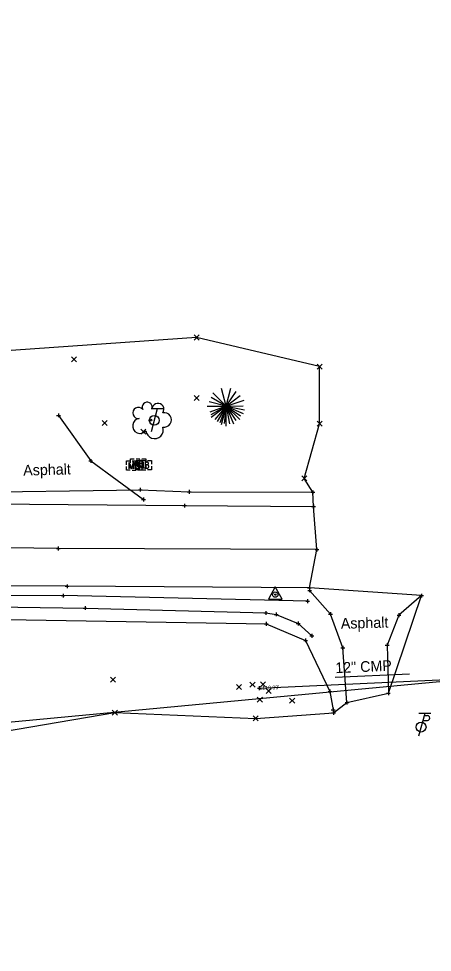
# Model space of a CAD drawing. Extents: x 146022 to 147632, y 437624 to 440659.
# Drawn here: x 147365.2 to 147473.8, y 438520.2 to 438765.5 of the extents above; entities that cross this region are included whole.
import ezdxf

# ---------------------------------------------------------------- set-up
doc = ezdxf.new("R2010")
doc.units = 0
for name, color, linetype in [('_CIVIL_CONSTRUCTION', 7, 'Continuous'), ('DR_P_Paved_Gutter', 7, 'Continuous'), ('DR_X_Storm_Sewer', 7, 'Continuous'), ('DR_X_Text', 7, 'Continuous'), ('DT_X_Contour_Major', 7, 'Continuous'), ('DT_X_Spot_Elev', 7, 'Continuous'), ('DT_X_Void', 7, 'Continuous'), ('PF_X_Ground_Line', 7, 'Continuous'), ('PV_P_Curb', 7, 'Continuous'), ('PV_P_Joint', 7, 'Continuous'), ('RD_P_Anchor_Assembly', 7, 'Continuous'), ('RD_P_GR_Lt_Replaced', 7, 'Continuous'), ('SC_Scratch1', 7, 'Continuous'), ('SC_Scratch3', 7, 'Continuous'), ('SV_X_Terrain_Boundary', 7, 'Continuous'), ('UT_X_Overhead_Cable_TV', 7, 'Continuous'), ('UT_X_Overhead_Electric', 7, 'Continuous')]:
    doc.layers.add(name, color=color, linetype=linetype)

msp = doc.modelspace()

# ---------------------------------------------------------------- linework, layer by layer
at = {"layer": '_CIVIL_CONSTRUCTION'}
for p, q in [((147411.27, 438681.05), (147412.61, 438682.38)), ((147411.27, 438682.38), (147412.61, 438681.05)), ((147379.11, 438675.34), (147380.44, 438676.67)), ((147379.11, 438676.67), (147380.44, 438675.34)), ((147443.56, 438673.4), (147444.89, 438674.73)), ((147443.56, 438674.73), (147444.89, 438673.4)), ((147411.28, 438665.13), (147412.61, 438666.46)), ((147411.28, 438666.46), (147412.61, 438665.13)), ((147387.13, 438658.62), (147388.46, 438659.95)), ((147387.13, 438659.95), (147388.46, 438658.62)), ((147443.58, 438658.4), (147444.91, 438659.73)), ((147443.58, 438659.73), (147444.91, 438658.4)), ((147397.27, 438656.35), (147398.6, 438657.68)), ((147397.27, 438657.68), (147398.6, 438656.35)), ((147439.54, 438644.06), (147440.88, 438645.39)), ((147439.54, 438645.39), (147440.88, 438644.06)), ((147389.33, 438591.14), (147390.66, 438592.48)), ((147389.33, 438592.48), (147390.66, 438591.14)), ((147422.38, 438589.28), (147423.71, 438590.61)), ((147422.38, 438590.61), (147423.71, 438589.28)), ((147425.94, 438589.88), (147427.27, 438591.22)), ((147425.94, 438591.22), (147427.27, 438589.88)), ((147428.71, 438589.94), (147430.04, 438591.28)), ((147428.71, 438591.28), (147430.04, 438589.94)), ((147430.16, 438588.2), (147431.5, 438589.53)), ((147430.16, 438589.53), (147431.5, 438588.2)), ((147427.87, 438585.93), (147429.2, 438587.27)), ((147427.87, 438587.27), (147429.2, 438585.93)), ((147436.36, 438585.66), (147437.7, 438587)), ((147436.36, 438587), (147437.7, 438585.66)), ((147389.8, 438582.52), (147391.14, 438583.85)), ((147389.8, 438583.85), (147391.14, 438582.52)), ((147426.81, 438581.01), (147428.14, 438582.34)), ((147426.81, 438582.34), (147428.14, 438581.01))]:
    msp.add_line(p, q, dxfattribs=at)
at = {"layer": 'DR_P_Paved_Gutter'}
msp.add_lwpolyline([(147090.74, 438611.98), (147096.12, 438612.12), (147118.78, 438612.16), (147162.43, 438612.19), (147208.09, 438612.03), (147262.63, 438611.82), (147323.61, 438611.5), (147382.66, 438610.66), (147430.09, 438609.36), (147432.84, 438608.99), (147438.6, 438606.61), (147442.2, 438603.35)], dxfattribs=at)
at = {"layer": 'DR_X_Storm_Sewer'}
for p in [(147070.7, 438553.26), (147428.39, 438589.62)]:
    msp.add_line(p, (147483.94, 438592.14), dxfattribs=at)
at = {"layer": 'DR_X_Text'}
msp.add_line((147467.8, 438593.31), (147448.35, 438592.43), dxfattribs=at)
at = {"layer": 'DT_X_Contour_Major'}
for p, q in [((147471.84, 438582.99), (147470.23, 438576.99)), ((147473.44, 438582.99), (147470.24, 438582.99)), ((147471.34, 438581.11), (147472.53, 438581.11)), ((147471.68, 438582.39), (147472.53, 438582.39))]:
    msp.add_line(p, q, dxfattribs=at)
msp.add_circle((147470.87, 438579.39), 1.3, dxfattribs=at)
msp.add_arc((147472.54, 438581.75), 0.638, 268.8767, 91.1233, dxfattribs=at)
at = {"layer": 'DT_X_Spot_Elev'}
for p, q in [((147395.01, 438649.28), (147396.01, 438649.28)), ((147396.07, 438649.81), (147397.07, 438649.81)), ((147397.56, 438649.42), (147398.57, 438649.42)), ((147395.01, 438646.84), (147396.01, 438646.84)), ((147395.52, 438648.06), (147395.52, 438648.06)), ((147396.07, 438647.36), (147397.07, 438647.36)), ((147396.58, 438648.58), (147396.58, 438648.58)), ((147397.56, 438646.97), (147398.57, 438646.97)), ((147398.08, 438648.2), (147398.08, 438648.2))]:
    msp.add_line(p, q, dxfattribs=at)
for points in [[(147393.52, 438648.31), (147393.52, 438649.28), (147394.49, 438649.28)], [(147394.23, 438647.26), (147394.23, 438648.86), (147394.81, 438647.26), (147395.36, 438648.86), (147395.36, 438647.26)], [(147394.58, 438648.84), (147394.58, 438649.81), (147395.55, 438649.81)], [(147395.28, 438647.78), (147395.28, 438649.38), (147395.86, 438647.78), (147396.42, 438649.38), (147396.42, 438647.78)], [(147396.54, 438648.13), (147396.61, 438648.19), (147396.65, 438648.23), (147396.67, 438648.27), (147396.68, 438648.29), (147396.71, 438648.34), (147396.72, 438648.38), (147396.75, 438648.47), (147396.75, 438648.51), (147396.75, 438648.56), (147396.73, 438648.63), (147396.71, 438648.7), (147396.67, 438648.75), (147396.61, 438648.8), (147396.56, 438648.82), (147396.53, 438648.84), (147396.47, 438648.86), (147395.85, 438648.86), (147395.85, 438647.26), (147396.54, 438647.26), (147396.63, 438647.31), (147396.71, 438647.37), (147396.77, 438647.48), (147396.81, 438647.59), (147396.82, 438647.7), (147396.82, 438647.78), (147396.8, 438647.85), (147396.75, 438647.97), (147396.68, 438648.04), (147396.54, 438648.13), (147395.85, 438648.13)], [(147396.08, 438648.45), (147396.08, 438649.42), (147397.05, 438649.42)], [(147396.53, 438649.28), (147397.52, 438649.28), (147397.52, 438648.31)], [(147396.78, 438647.4), (147396.78, 438649), (147397.36, 438647.4), (147397.91, 438649), (147397.91, 438647.4)], [(147397.6, 438648.65), (147397.67, 438648.72), (147397.7, 438648.75), (147397.73, 438648.79), (147397.74, 438648.82), (147397.77, 438648.87), (147397.78, 438648.91), (147397.8, 438648.99), (147397.8, 438649.03), (147397.8, 438649.08), (147397.79, 438649.16), (147397.77, 438649.22), (147397.73, 438649.27), (147397.67, 438649.32), (147397.61, 438649.35), (147397.59, 438649.36), (147397.53, 438649.38), (147396.91, 438649.38), (147396.91, 438647.78), (147397.6, 438647.78), (147397.69, 438647.83), (147397.77, 438647.9), (147397.83, 438648), (147397.87, 438648.11), (147397.88, 438648.23), (147397.88, 438648.3), (147397.85, 438648.38), (147397.8, 438648.49), (147397.74, 438648.57), (147397.6, 438648.65), (147396.91, 438648.65)], [(147397.59, 438649.81), (147398.58, 438649.81), (147398.58, 438648.84)], [(147399.1, 438648.26), (147399.16, 438648.33), (147399.2, 438648.37), (147399.22, 438648.4), (147399.24, 438648.43), (147399.26, 438648.48), (147399.27, 438648.52), (147399.3, 438648.6), (147399.3, 438648.64), (147399.3, 438648.69), (147399.29, 438648.77), (147399.26, 438648.83), (147399.22, 438648.88), (147399.16, 438648.93), (147399.11, 438648.96), (147399.08, 438648.97), (147399.02, 438649), (147398.4, 438649), (147398.4, 438647.4), (147399.1, 438647.4), (147399.18, 438647.45), (147399.26, 438647.51), (147399.32, 438647.61), (147399.36, 438647.72), (147399.37, 438647.84), (147399.37, 438647.91), (147399.35, 438647.99), (147399.3, 438648.1), (147399.24, 438648.18), (147399.1, 438648.26), (147398.4, 438648.26)], [(147399.08, 438649.42), (147400.08, 438649.42), (147400.08, 438648.45)], [(147394.49, 438646.84), (147393.52, 438646.84), (147393.52, 438647.81)], [(147395.55, 438647.36), (147394.58, 438647.36), (147394.58, 438648.33)], [(147397.05, 438646.97), (147396.08, 438646.97), (147396.08, 438647.94)], [(147397.52, 438647.81), (147397.52, 438646.84), (147396.53, 438646.84)], [(147398.58, 438648.33), (147398.58, 438647.36), (147397.59, 438647.36)], [(147400.08, 438647.94), (147400.08, 438646.97), (147399.08, 438646.97)]]:
    msp.add_lwpolyline(points, dxfattribs=at)
at = {"layer": 'DT_X_Void'}
for p, q in [((147419.68, 438663.68), (147418.45, 438668.29)), ((147419.68, 438663.68), (147420.94, 438668.38)), ((147419.68, 438663.68), (147415.77, 438665.98)), ((147419.68, 438663.68), (147416.19, 438667.17)), ((147419.68, 438663.68), (147422.34, 438667.57)), ((147419.68, 438663.68), (147423.34, 438666.49)), ((147414.75, 438663.68), (147419.68, 438663.68)), ((147419.68, 438663.68), (147415.27, 438664.86)), ((147419.68, 438663.68), (147415.39, 438662.12)), ((147419.68, 438663.68), (147415.7, 438661.4)), ((147419.68, 438663.68), (147415.77, 438660.69)), ((147419.68, 438663.68), (147416.74, 438660.21)), ((147419.68, 438663.68), (147417.36, 438659.67)), ((147419.68, 438663.68), (147418.02, 438659.34)), ((147419.68, 438663.68), (147418.42, 438658.82)), ((147419.68, 438663.68), (147419.14, 438659.09)), ((147419.68, 438663.68), (147424.42, 438665.29)), ((147419.68, 438663.68), (147424.19, 438663.77)), ((147419.68, 438658.44), (147419.68, 438663.68)), ((147419.68, 438663.68), (147420.6, 438659.04)), ((147419.68, 438663.68), (147421.61, 438659.01)), ((147419.68, 438663.68), (147422.22, 438659.89)), ((147419.68, 438663.68), (147423.27, 438660.16)), ((147419.68, 438663.68), (147423.5, 438661.13)), ((147419.68, 438663.68), (147424.15, 438661.74)), ((147419.68, 438663.68), (147424.51, 438662.72))]:
    msp.add_line(p, q, dxfattribs=at)
msp.add_circle((147399.96, 438660.03), 0.24, dxfattribs=at)
for centre, radius, start, end in [((147396.65, 438661.9), 1.47, 39.0625, 279.5412), ((147398.98, 438663.4), 1.32, 354.0047, 205.9741), ((147401.79, 438662.86), 1.55, 323.83, 165.0376), ((147403.42, 438660.07), 1.91, 259.1453, 101.4596), ((147397.11, 438658.48), 1.97, 96.1722, 320.5737), ((147400.91, 438657.43), 2.28, 184.9476, 19.4572)]:
    msp.add_arc(centre, radius, start, end, dxfattribs=at)
at = {"layer": 'PF_X_Ground_Line'}
msp.add_lwpolyline([(147090.56, 438608.28), (147100.12, 438605.93), (147134.16, 438606.88), (147169.46, 438609.09), (147200.89, 438609.42), (147231.43, 438607.76), (147285.62, 438608.05), (147340.88, 438607.99), (147430.19, 438606.52), (147440.56, 438602.17), (147446.94, 438588.76), (147447.8, 438583.92), (147447.86, 438583.13)], dxfattribs=at)
at = {"layer": 'PV_P_Curb'}
msp.add_lwpolyline([(147443.52, 438625.99), (147375.64, 438626.29), (147305.7, 438627.27), (147243.72, 438626.94), (147218.64, 438627.35)], dxfattribs=at)
at = {"layer": 'PV_P_Joint'}
msp.add_lwpolyline([(147430.78, 438613.01), (147434.38, 438613.01), (147432.58, 438616.23)], close=True, dxfattribs=at)
for radius in [0.7, 0.16]:
    msp.add_circle((147432.58, 438614.17), radius, dxfattribs=at)
at = {"layer": 'RD_P_Anchor_Assembly'}
for p, q in [((147375.18, 438661.25), (147376.18, 438661.25)), ((147375.68, 438661.75), (147375.68, 438660.75)), ((147375.68, 438661.25), (147375.68, 438661.25)), ((147383.64, 438649.3), (147384.64, 438649.3)), ((147384.14, 438649.8), (147384.14, 438648.8)), ((147384.14, 438649.3), (147384.14, 438649.3)), ((147396.66, 438641.73), (147397.66, 438641.73)), ((147397.16, 438642.23), (147397.16, 438641.23)), ((147397.16, 438641.73), (147397.16, 438641.73)), ((147409.97, 438641.67), (147409.97, 438640.67)), ((147442.47, 438641.55), (147442.47, 438640.55)), ((147397.5, 438639.17), (147398.5, 438639.17)), ((147398, 438639.67), (147398, 438638.67)), ((147398, 438639.17), (147398, 438639.17)), ((147409.47, 438641.17), (147410.47, 438641.17)), ((147409.97, 438641.17), (147409.97, 438641.17)), ((147441.97, 438641.05), (147442.97, 438641.05)), ((147442.47, 438641.05), (147442.47, 438641.05)), ((147408.26, 438637.55), (147409.26, 438637.55)), ((147408.76, 438638.05), (147408.76, 438637.05)), ((147408.76, 438637.55), (147408.76, 438637.55)), ((147442.13, 438637.34), (147443.13, 438637.34)), ((147442.63, 438637.84), (147442.63, 438636.84)), ((147442.63, 438637.34), (147442.63, 438637.34)), ((147375.64, 438626.79), (147375.64, 438625.79)), ((147375.14, 438626.29), (147376.14, 438626.29)), ((147375.64, 438626.29), (147375.64, 438626.29)), ((147443.02, 438625.99), (147444.02, 438625.99)), ((147443.52, 438626.49), (147443.52, 438625.49)), ((147443.52, 438625.99), (147443.52, 438625.99)), ((147377.93, 438616.86), (147377.93, 438615.86)), ((147376.87, 438614.41), (147376.87, 438613.41)), ((147377.43, 438616.36), (147378.43, 438616.36)), ((147377.93, 438616.36), (147377.93, 438616.36)), ((147441.04, 438616), (147442.04, 438616)), ((147441.1, 438615.29), (147442.1, 438615.29)), ((147441.54, 438616.5), (147441.54, 438615.5)), ((147441.54, 438616), (147441.54, 438616)), ((147441.6, 438615.79), (147441.6, 438614.79)), ((147441.6, 438615.29), (147441.6, 438615.29)), ((147470.97, 438614.42), (147470.97, 438613.42)), ((147376.37, 438613.91), (147377.37, 438613.91)), ((147376.87, 438613.91), (147376.87, 438613.91)), ((147440.58, 438612.46), (147441.58, 438612.46)), ((147441.08, 438612.96), (147441.08, 438611.96)), ((147441.08, 438612.46), (147441.08, 438612.46)), ((147470.47, 438613.92), (147471.47, 438613.92)), ((147470.97, 438613.92), (147470.97, 438613.92)), ((147382.16, 438610.66), (147383.16, 438610.66)), ((147382.66, 438611.16), (147382.66, 438610.16)), ((147382.66, 438610.66), (147382.66, 438610.66)), ((147430.09, 438609.86), (147430.09, 438608.86)), ((147432.84, 438609.49), (147432.84, 438608.49)), ((147447.07, 438609.58), (147447.07, 438608.58)), ((147429.59, 438609.36), (147430.59, 438609.36)), ((147430.09, 438609.36), (147430.09, 438609.36)), ((147430.19, 438607.02), (147430.19, 438606.02)), ((147432.34, 438608.99), (147433.34, 438608.99)), ((147432.84, 438608.99), (147432.84, 438608.99)), ((147438.6, 438607.11), (147438.6, 438606.11)), ((147446.57, 438609.08), (147447.57, 438609.08)), ((147447.07, 438609.08), (147447.07, 438609.08)), ((147464.55, 438608.79), (147465.55, 438608.79)), ((147465.05, 438609.29), (147465.05, 438608.29)), ((147465.05, 438608.79), (147465.05, 438608.79)), ((147429.69, 438606.52), (147430.69, 438606.52)), ((147430.19, 438606.52), (147430.19, 438606.52)), ((147438.1, 438606.61), (147439.1, 438606.61)), ((147438.6, 438606.61), (147438.6, 438606.61)), ((147440.06, 438602.17), (147441.06, 438602.17)), ((147440.56, 438602.67), (147440.56, 438601.67)), ((147440.56, 438602.17), (147440.56, 438602.17)), ((147441.7, 438603.35), (147442.7, 438603.35)), ((147442.2, 438603.85), (147442.2, 438602.85)), ((147442.2, 438603.35), (147442.2, 438603.35)), ((147449.84, 438600.23), (147450.84, 438600.23)), ((147450.34, 438600.73), (147450.34, 438599.73)), ((147450.34, 438600.23), (147450.34, 438600.23)), ((147461.45, 438600.89), (147462.45, 438600.89)), ((147461.95, 438601.39), (147461.95, 438600.39)), ((147461.95, 438600.89), (147461.95, 438600.89)), ((147446.44, 438588.76), (147447.44, 438588.76)), ((147446.94, 438589.26), (147446.94, 438588.26)), ((147446.94, 438588.76), (147446.94, 438588.76)), ((147461.79, 438588.25), (147462.79, 438588.25)), ((147462.29, 438588.75), (147462.29, 438587.75)), ((147462.29, 438588.25), (147462.29, 438588.25)), ((147450.91, 438585.81), (147451.91, 438585.81)), ((147451.41, 438586.31), (147451.41, 438585.31)), ((147451.41, 438585.81), (147451.41, 438585.81)), ((147447.3, 438583.92), (147448.3, 438583.92)), ((147447.36, 438583.13), (147448.36, 438583.13)), ((147447.8, 438584.42), (147447.8, 438583.42)), ((147447.8, 438583.92), (147447.8, 438583.92)), ((147447.86, 438583.63), (147447.86, 438582.63)), ((147447.86, 438583.13), (147447.86, 438583.13))]:
    msp.add_line(p, q, dxfattribs=at)
at = {"layer": 'RD_P_GR_Lt_Replaced'}
for points in [[(147168.32, 438765.47), (147172.75, 438740.93), (147180.87, 438702.22), (147190.04, 438671.47), (147197.36, 438659.31), (147205.75, 438651.31), (147223.43, 438643.49), (147231.5, 438641.71), (147288.88, 438640.47), (147347.57, 438641.04), (147397.16, 438641.73), (147409.97, 438641.17), (147442.47, 438641.05)], [(147441.08, 438612.46), (147376.87, 438613.91), (147318.39, 438613.89), (147243.87, 438614.42), (147218.85, 438614.27), (147160.23, 438614.06), (147116.28, 438615.1), (147116.37, 438616.32), (147097.65, 438616.22), (147092.09, 438613.53), (147091.95, 438613.68)]]:
    msp.add_lwpolyline(points, dxfattribs=at)
at = {"layer": 'SC_Scratch1'}
for points in [[(147375.68, 438661.25), (147384.14, 438649.3), (147398, 438639.17)], [(147451.41, 438585.81), (147450.34, 438600.23), (147447.07, 438609.08), (147441.6, 438615.29)], [(147470.97, 438613.92), (147465.05, 438608.79), (147461.95, 438600.89), (147462.29, 438588.25)]]:
    msp.add_lwpolyline(points, dxfattribs=at)
at = {"layer": 'SC_Scratch3'}
for points in [[(147231.86, 438637.99), (147288.59, 438637.9), (147347.36, 438637.73), (147357.85, 438637.99), (147408.76, 438637.55), (147442.63, 438637.34)], [(147441.54, 438616), (147377.93, 438616.36), (147319.33, 438616.54), (147244.05, 438616.81), (147219.36, 438616.86), (147159.11, 438616.91), (147088.59, 438616.85)]]:
    msp.add_lwpolyline(points, dxfattribs=at)
at = {"layer": 'SV_X_Terrain_Boundary'}
msp.add_lwpolyline([(147113.81, 438520.22), (147177.01, 438554.45), (147231.16, 438565.21), (147265.76, 438561.91), (147390.47, 438583.18), (147427.48, 438581.67), (147447.86, 438583.13), (147451.41, 438585.81), (147462.29, 438588.25), (147470.97, 438613.92), (147441.54, 438616), (147443.52, 438625.99), (147442.63, 438637.34), (147442.47, 438641.05), (147440.21, 438644.72), (147444.24, 438659.07), (147444.23, 438674.06), (147411.94, 438681.71), (147340.71, 438676.77), (147269.57, 438686.84), (147201.59, 438744.19), (147187.75, 438754.72), (147168.32, 438765.47), (147156.85, 438763.96)], dxfattribs=at)
at = {"layer": 'UT_X_Overhead_Cable_TV'}
for p, q in [((147401.62, 438662.95), (147400.01, 438656.95)), ((147403.22, 438662.95), (147400.02, 438662.95))]:
    msp.add_line(p, q, dxfattribs=at)
msp.add_circle((147400.82, 438659.95), 1.3, dxfattribs=at)
at = {"layer": 'UT_X_Overhead_Electric'}
for p, q in [((147428.39, 438590.12), (147428.39, 438589.12)), ((147427.89, 438589.62), (147428.89, 438589.62)), ((147428.39, 438589.62), (147428.39, 438589.62))]:
    msp.add_line(p, q, dxfattribs=at)

# ---------------------------------------------------------------- texts
at = {"layer": 'DR_X_Text'}
for s, rotation, p in [('Asphalt', 1.4771, (147366.46, 438645.44)), ('Asphalt', 1.4771, (147449.82, 438605.2)), ('12" CMP', 2.6015, (147448.41, 438593.53))]:
    msp.add_text(s, height=2.8, rotation=rotation, dxfattribs=at).set_placement(p)
at = {"layer": 'SC_Scratch1'}
msp.add_text("1119.99'", height=1, rotation=2.6015, dxfattribs=at).set_placement((147428.41, 438589.12))

doc.saveas('drawing.dxf')
